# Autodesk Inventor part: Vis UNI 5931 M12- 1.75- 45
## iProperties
Shininess: 64.0
Length Units: 11269
Angle Units: 11279
Time Units: 11290
Mass Units: 11283
Length Display Precision: 3
Angle Display Precision: 2
Compacted: True
Part Number: Vis UNI 5931 M12- 1.75- 45
Document SubType Name: Modeling
Created: 2005-02
Material: Par défaut
Designer: LEGERET Philippe
Catalog Web Link: www.traceparts.com
Description: Vis Cylindrique hexagonale creuse UNI 5931 - M12x1.75x45 - 8.8
Density: 0.0
Volumn: 0.0
Area: 0.0
PropertySet Name: Model Information
Control State: 0
Master: False
Checked Out: False
Author: Trace Parts S.A.
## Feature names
1. Base1
